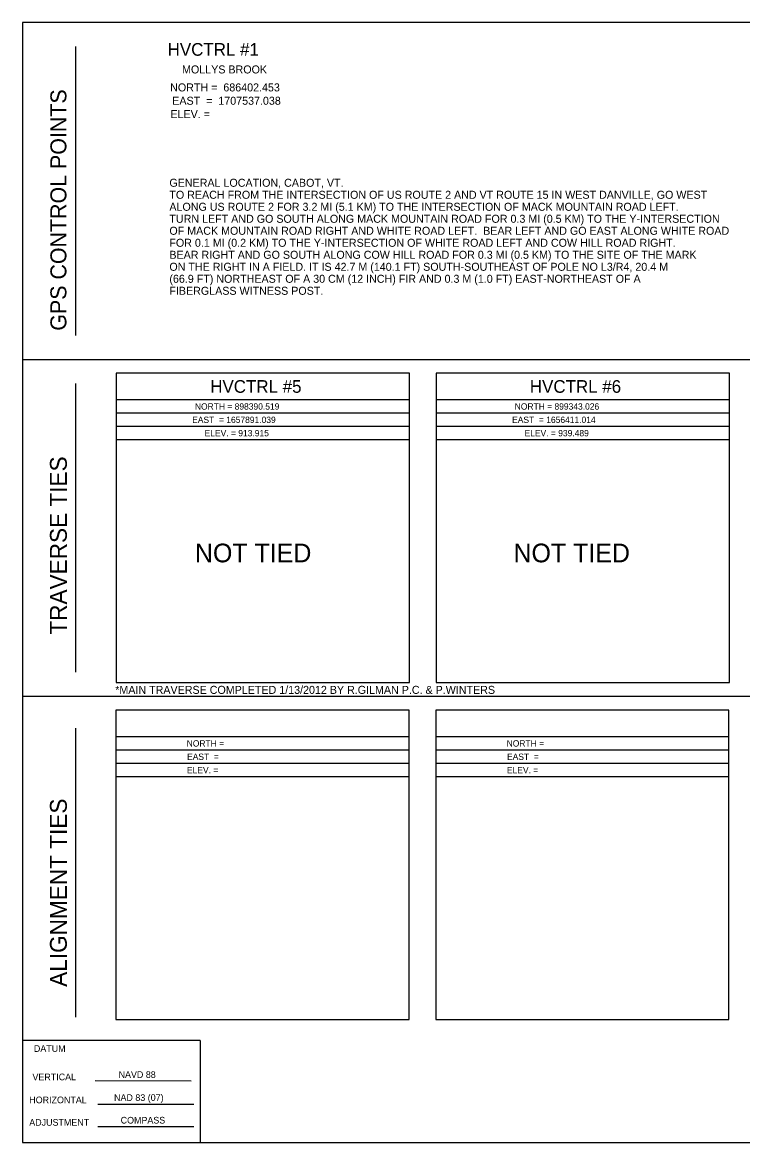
# Model space of a CAD drawing. Extents: x 1702290 to 1703620, y 686233 to 686653.
# Drawn here: x 1702290.5 to 1702560.6, y 686232.9 to 686652.9 of the extents above; entities that cross this region are included whole.
import ezdxf

# ---------------------------------------------------------------- set-up
doc = ezdxf.new("R2010")
doc.units = 0
for name, color, linetype in [('Default', 7, 'Continuous'), ('NBL1', 7, 'Continuous'), ('NBL2', 7, 'Continuous')]:
    doc.layers.add(name, color=color, linetype=linetype)

msp = doc.modelspace()

# ---------------------------------------------------------------- linework, layer by layer
at = {"layer": 'NBL1'}
for p, q in [((1702435.72, 686511.4), (1702325.72, 686511.4)), ((1702555.72, 686511.4), (1702445.72, 686511.4)), ((1702435.72, 686506.4), (1702325.72, 686506.4)), ((1702555.72, 686506.4), (1702445.72, 686506.4)), ((1702435.72, 686501.4), (1702325.72, 686501.4)), ((1702555.72, 686501.4), (1702445.72, 686501.4)), ((1702435.72, 686496.4), (1702325.72, 686496.4)), ((1702555.72, 686496.4), (1702445.72, 686496.4)), ((1702435.49, 686385.06), (1702325.49, 686385.06)), ((1702555.49, 686385.06), (1702445.49, 686385.06)), ((1702435.49, 686380.06), (1702325.49, 686380.06)), ((1702555.49, 686380.06), (1702445.49, 686380.06)), ((1702435.49, 686375.06), (1702325.49, 686375.06)), ((1702555.49, 686375.06), (1702445.49, 686375.06)), ((1702435.49, 686370.06), (1702325.49, 686370.06)), ((1702555.49, 686370.06), (1702445.49, 686370.06))]:
    msp.add_line(p, q, dxfattribs=at)
for points in [[(1702290.49, 686232.9), (1702930.49, 686232.9), (1702930.49, 686652.9), (1702290.49, 686652.9)], [(1702325.72, 686405.4), (1702435.72, 686405.4), (1702435.72, 686521.4), (1702325.72, 686521.4)], [(1702445.72, 686405.4), (1702555.72, 686405.4), (1702555.72, 686521.4), (1702445.72, 686521.4)], [(1702325.49, 686279.06), (1702435.49, 686279.06), (1702435.49, 686395.06), (1702325.49, 686395.06)], [(1702445.49, 686279.06), (1702555.49, 686279.06), (1702555.49, 686395.06), (1702445.49, 686395.06)]]:
    msp.add_lwpolyline(points, close=True, dxfattribs=at)
at = {"layer": 'NBL2'}
for p, q in [((1702310.49, 686535.56), (1702310.49, 686643.9)), ((1702290.49, 686526.56), (1702930.49, 686526.56)), ((1702310.49, 686409.23), (1702310.49, 686517.56)), ((1702290.49, 686400.23), (1702930.49, 686400.23)), ((1702310.49, 686279.9), (1702310.49, 686388.23)), ((1702357.16, 686271.15), (1702290.49, 686271.15)), ((1702357.16, 686271.15), (1702357.16, 686232.9)), ((1702357.16, 686271.15), (1702357.16, 686232.9)), ((1702317.73, 686256.13), (1702353.73, 686256.09)), ((1702318.84, 686247.35), (1702354.84, 686247.35)), ((1702318.84, 686238.92), (1702354.84, 686238.88))]:
    msp.add_line(p, q, dxfattribs=at)

# ---------------------------------------------------------------- texts
at = {"layer": 'Default'}
for s, height, p in [('GENERAL LOCATION, CABOT, VT.', 3, (1702345.62, 686591.27)), ('TO REACH FROM THE INTERSECTION OF US ROUTE 2 AND VT ROUTE 15 IN WEST DANVILLE, GO WEST ', 3, (1702345.62, 686586.77)), ('ALONG US ROUTE 2 FOR 3.2 MI (5.1 KM) TO THE INTERSECTION OF MACK MOUNTAIN ROAD LEFT.  ', 3, (1702345.62, 686582.27)), ('TURN LEFT AND GO SOUTH ALONG MACK MOUNTAIN ROAD FOR 0.3 MI (0.5 KM) TO THE Y-INTERSECTION ', 3, (1702345.62, 686577.77)), ('OF MACK MOUNTAIN ROAD RIGHT AND WHITE ROAD LEFT.  BEAR LEFT AND GO EAST ALONG WHITE ROAD ', 3, (1702345.62, 686573.27)), ('FOR 0.1 MI (0.2 KM) TO THE Y-INTERSECTION OF WHITE ROAD LEFT AND COW HILL ROAD RIGHT.  ', 3, (1702345.62, 686568.77)), ('BEAR RIGHT AND GO SOUTH ALONG COW HILL ROAD FOR 0.3 MI (0.5 KM) TO THE SITE OF THE MARK ', 3, (1702345.62, 686564.27)), ('ON THE RIGHT IN A FIELD. IT IS 42.7 M (140.1 FT) SOUTH-SOUTHEAST OF POLE NO L3/R4, 20.4 M ', 3, (1702345.62, 686559.77)), ('(66.9 FT) NORTHEAST OF A 30 CM (12 INCH) FIR AND 0.3 M (1.0 FT) EAST-NORTHEAST OF A ', 3, (1702345.62, 686555.27)), ('FIBERGLASS WITNESS POST.', 3, (1702345.62, 686550.77)), ('NOT TIED', 7, (1702355.2, 686450.47)), ('NOT TIED', 7, (1702474.67, 686450.47)), ('*MAIN TRAVERSE COMPLETED 1/13/2012 BY R.GILMAN P.C. & P.WINTERS', 3, (1702325.31, 686401.14))]:
    msp.add_text(s, height=height, dxfattribs=at).set_placement(p)
at = {"layer": 'NBL1'}
for s, height, p in [('HVCTRL #5', 4.75, (1702360.94, 686514.02)), ('HVCTRL #6', 4.75, (1702480.81, 686514.02)), ('NORTH = 898390.519', 2.375, (1702355.19, 686507.71)), ('NORTH = 899343.026', 2.375, (1702475.14, 686507.71)), ('EAST  = 1657891.039', 2.375, (1702354.16, 686502.71)), ('EAST  = 1656411.014', 2.375, (1702474.16, 686502.71)), ('ELEV. = 913.915', 2.375, (1702358.84, 686497.71)), ('ELEV. = 939.489', 2.375, (1702478.83, 686497.71)), ('NORTH =             ', 2.375, (1702352.11, 686381.38)), ('NORTH =             ', 2.375, (1702472.11, 686381.38)), ('EAST  =             ', 2.375, (1702352.25, 686376.38)), ('EAST  =             ', 2.375, (1702472.25, 686376.38)), ('ELEV. =             ', 2.375, (1702352.22, 686371.38)), ('ELEV. =             ', 2.375, (1702472.22, 686371.38))]:
    msp.add_text(s, height=height, dxfattribs=at).set_placement(p)
msp.add_text('ALIGNMENT TIES', height=6.3332, rotation=90, dxfattribs=at).set_placement((1702307.16, 686291.3))
at = {"layer": 'NBL2'}
for s, height, p in [('     HVCTRL #1     ', 4.75, (1702336.14, 686640.39)), ('    MOLLYS BROOK    ', 3, (1702345.91, 686633.76)), ('NORTH =  686402.453 ', 3, (1702345.91, 686627.02)), ('EAST  =  1707537.038', 3, (1702346.7, 686622.02)), ('ELEV. =             ', 3, (1702346.02, 686617.02)), ('DATUM', 2.5, (1702294.81, 686266.91)), ('  NAVD 88 ', 2.5, (1702324.71, 686257.14)), ('NAD 83 (07)', 2.5, (1702324.87, 686248.52)), ('HORIZONTAL', 2.5, (1702293.07, 686247.65)), ('  COMPASS ', 2.5, (1702325.49, 686240.04)), ('ADJUSTMENT', 2.5, (1702293.07, 686239.21))]:
    msp.add_text(s, height=height, dxfattribs=at).set_placement(p)
for s, height, rotation, p in [('GPS CONTROL POINTS', 6, 90, (1702306.99, 686537.31)), ('TRAVERSE TIES', 6.3332, 90, (1702307.16, 686423.36)), ('VERTICAL', 2.5, 0.1439, (1702294.27, 686256.24))]:
    msp.add_text(s, height=height, rotation=rotation, dxfattribs=at).set_placement(p)

doc.saveas('drawing.dxf')
